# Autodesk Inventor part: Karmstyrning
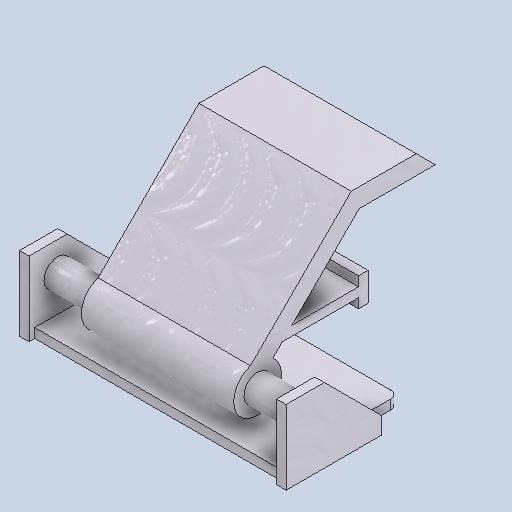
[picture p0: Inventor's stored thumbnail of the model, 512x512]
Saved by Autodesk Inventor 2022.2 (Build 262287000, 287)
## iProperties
Created: 2019-06
Part Number: Karmstyrning
Material: Aluminum 6061, Welded
Document SubType Name: Modeling
Designer: cl
Density: 2.7 g/cm^3
Appearance: Weld - Aluminum
Author: cl
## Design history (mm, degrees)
sketch "Sketch1"
  geometry: L1 (0, 0)-(0, -50); L2 (0, -50)-(4, -50); L3 (4, -50)-(4, -61); L4 (8, -65)-(122, -65); L5 (126, -61)-(126, -50); L6 (126, -50)-(130, -50); L7 (130, -50)-(130, 0); L8 (130, 0)-(0, 0); A1 r 4 centre (122, -61) between (122, -65) and (126, -61); A2 r 4 centre (8, -61) between (4, -61) and (8, -65); 2 further points
  constraints: 16 end point, 6 point on line, 5 perpendicular, 4 point on circle, 4 tangent, 2 centre point, 1 equal radius, 1 vertical
  dimensions: "d4" = 15 distance of L2.end point (4, -65); "d6" = 15 distance of point (126, -65) L5.end; "d8" = 4 radius of A1; "d14" = 50 distance of L1.start L1.end; "d28" = 130 distance between parallel lines of L7 L1; "d29" = 122 distance of L5.end L2.end; "d32" = 4 distance of L1.end L2.end
extrude "Extrusion1" new body sketch "Sketch1" distance "d9" = 5; taper "d10" = 0 deg
sketch "Sketch4"
  geometry: L1 (0, 0)-(50, 0) reference; L2 (0, 0)-(-3, 0); L3 (-3, 0)-(-3, 39); L4 (17, 39)-(46.414, 9.586); L5 (47, 8.172)-(47, 0); L6 (50, 0)-(61, 0) reference; L7 (0, 0)-(47, 0); L8 (-3, 39)-(17, 39); L9 (-3, 39)-(17, 39); A1 r 2 centre (45, 8.172) between (47, 8.172) and (46.414, 9.586); 1 further point
  constraints: 14 end point, 4 horizontal, 3 point on line, 2 point on circle, 2 tangent, 1 centre point, 1 collinear, 1 perpendicular, 1 vertical
  dimensions: "d15" = 3 distance of L1.start L2.end; "d19" = 9 distance of point (47, 9) L5.end; "d20" = 2 radius of A1 (derived); "d21" = 50 distance from line of L5 L2.end; "d34" = 39 distance of L2.end L3.end; "d35" = 20 distance of L3.end L4.start
extrude "Extrusion2" join sketch "Sketch4" distance "d22" = 5; taper "d23" = 0 deg
sketch "Sketch7"
  geometry: L1 (-3, 39)-(-3, 0) reference; L2 (17, 39)-(-3, 39) reference; C1 r 7.2 at (12, 24); 1 further point
  constraints: 1 centre point
  dimensions: "d39" = 14.4 diameter of C1; "d40" = 15 distance from line of L1 C1.centre; "d41" = 15 distance from line of L2 C1.centre
extrude "Extrusion4" join sketch "Sketch7" distance "d42" = 140; taper "d43" = 0 deg
workplane "Work Plane2"
mirror "Mirror2"
sketch "Sketch8"
  geometry: L1 (33.563, -20.05)-(38.512, -25); L2 (38.512, -25)-(38.512, -65); L3 (38.512, -65)-(33.512, -65); L4 (33.512, -65)-(33.512, -70); L5 (33.512, -70)-(48.512, -70); L6 (48.512, -70)-(48.512, -65); L7 (48.512, -65)-(43.512, -65); L8 (43.512, -65)-(43.512, -30); L9 (43.512, -30)-(78.868, -65.355); L10 (78.868, -65.355)-(78.868, -105.355); L11 (78.868, -105.355)-(88.868, -95.355); L12 (88.868, -95.355)-(88.868, -61.213); L13 (88.868, -61.213)-(35.933, -8.279); L14 (0, -65)-(5, -65) reference; C1 r 7.2 at (24, -12) reference; A1 r 12.5 centre (24, -12) between (35.933, -8.279) and (33.563, -20.05); 1 further point
  constraints: 26 end point, 6 perpendicular, 2 parallel, 2 point on circle, 1 centre point, 1 coincident, 1 collinear, 1 horizontal, 1 vertical
  dimensions: "d74" = 25 diameter of A1; "d75" = 7 distance of L1.start L1.end; "d76" = 40 distance of L1.end L2.end; "d77" = 5 distance of L2.end L3.end; "d78" = 5 distance of L3.end L4.end; "d79" = 15 distance of L4.end L5.end; "d80" = 135 deg angle of L1 L2; "d81" = 5 distance of L6.end L7.end; "d82" = 35 distance of L7.end L8.end; "d83" = 50 distance of L8.end L9.end; "d84" = 45 deg angle of L8 L9; "d85" = 40 distance of L9.end L10.end; "d86" = 45 deg angle of L11 L10; "d87" = 10 distance between parallel lines of L12 L10; "d88" = 5 distance of L5.end L6.end; "d89" = 10 distance between parallel lines of L13 L9
extrude "Extrusion5" join sketch "Sketch8" stored distance "d72" = 80; taper "d73" = 0 deg
body "Solid1"
other parameters: "d44" = -65
